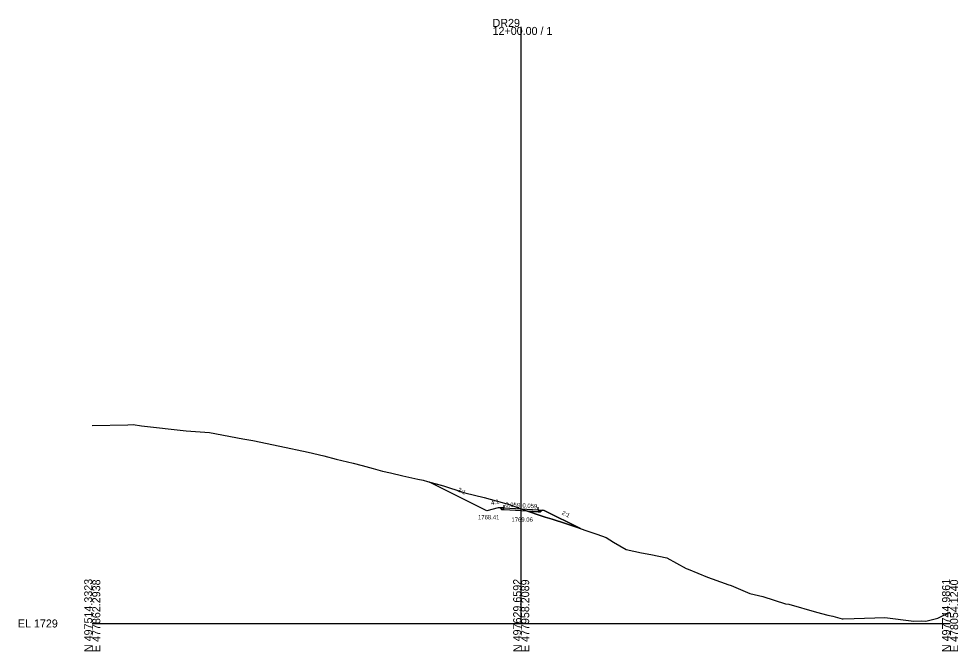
# Model space of a CAD drawing. Extents: x -26 to 303, y -10 to 4734.
# Drawn here: x -25.7 to 302.8, y 3990.3 to 4211.4 of the extents above; entities that cross this region are included whole.
import ezdxf

# ---------------------------------------------------------------- set-up
doc = ezdxf.new("R2010")
doc.units = 0
for name, color, linetype in [('Exist Cross Section Cell', 7, 'Continuous'), ('Exist XS Center Line Elevation Label', 7, 'Continuous'), ('Exist XS Ground Line', 7, 'Continuous'), ('Prop XS Ditch Slope Text', 7, 'Continuous'), ('Prop XS Ditch Standard Text', 7, 'Continuous'), ('Prop XS Dump Level', 7, 'Continuous'), ('Prop XS Earthwork Shape', 7, 'Continuous'), ('Prop XS EOT Tick Mark', 7, 'Continuous'), ('Prop XS Finish Grade', 7, 'Continuous'), ('Prop XS Finish Grade Earthwork', 7, 'Continuous'), ('Prop XS Finish Grade Pavement', 7, 'Continuous'), ('Prop XS Pvmt Edge Slope', 7, 'Continuous'), ('Prop XS SE Text', 7, 'Continuous'), ('Prop XS Shoulder Borrow Shape', 7, 'Continuous'), ('Prop XS Side Slope Text', 7, 'Continuous'), ('Prop XS Subgrade Earthwork', 7, 'Continuous')]:
    doc.layers.add(name, color=color, linetype=linetype)

msp = doc.modelspace()

# ---------------------------------------------------------------- linework, layer by layer
at = {"layer": 'Exist Cross Section Cell'}
for p, q in [((150, 4000), (150, 4208.57)), ((0, 4000), (150, 4000)), ((150, 4000), (300, 4000))]:
    msp.add_line(p, q, dxfattribs=at)
at = {"layer": 'Exist XS Ground Line'}
msp.add_lwpolyline([(0, 4069.23), (12.42, 4069.51), (14.36, 4069.52), (17.18, 4069.08), (32.86, 4067.4), (41.05, 4066.76), (52.7, 4064.58), (56.11, 4063.98), (65.64, 4062.03), (75.53, 4059.86), (80.98, 4058.57), (85.35, 4057.44), (91.27, 4056.08), (94.44, 4055.28), (98.25, 4054.18), (101.54, 4053.27), (104.28, 4052.64), (108.65, 4051.64), (113.89, 4050.5), (115.75, 4050.05), (117.29, 4049.63), (122.85, 4048.07), (129.54, 4045.91), (129.95, 4045.78), (130.3, 4045.72), (137.05, 4044.01), (143.31, 4042.31), (144.16, 4042.12), (145.18, 4041.78), (150, 4040.06), (151.26, 4039.61), (156.32, 4037.84), (158.36, 4037.17), (160.82, 4036.44), (165.46, 4034.97), (169.33, 4033.67), (172.57, 4032.53), (176.46, 4031.27), (179.67, 4030.04), (182.34, 4028.39), (186.77, 4025.87), (192.1, 4024.67), (195.34, 4024.08), (200.97, 4023), (207.75, 4019.24), (208.35, 4018.94), (215.18, 4016.16), (221.36, 4013.99), (222.28, 4013.68), (223.39, 4013.29), (229.99, 4010.47), (234.53, 4009.41), (242.48, 4006.88), (243.62, 4006.72), (253.33, 4003.94), (257.21, 4002.85), (258.4, 4002.68), (259, 4002.54), (262.23, 4001.64), (262.59, 4001.65), (266.41, 4001.76), (273.72, 4002.01), (277.23, 4002.07), (287.27, 4000.82), (290.05, 4000.91), (291.51, 4000.86), (295.69, 4001.81), (300, 4003.96)], dxfattribs=at)
at = {"layer": 'Prop XS Dump Level'}
for p, q in [((144, 4040.41), (150, 4040.06)), ((150, 4040.06), (156, 4039.7))]:
    msp.add_line(p, q, dxfattribs=at)
at = {"layer": 'Prop XS Earthwork Shape'}
for points in [[(138, 4039.41), (117.92, 4049.45), (122.85, 4048.07), (129.54, 4045.91), (129.95, 4045.78), (130.3, 4045.72), (137.05, 4044.01), (143.31, 4042.31), (144.16, 4042.12), (145.18, 4041.78), (150, 4040.06), (151.26, 4039.61), (152.27, 4039.25), (150, 4039.39), (144, 4039.74), (143.37, 4039.78), (142.74, 4040.41), (142, 4040.41)], [(138, 4039.41), (117.92, 4049.45), (122.85, 4048.07), (129.54, 4045.91), (129.95, 4045.78), (130.3, 4045.72), (137.05, 4044.01), (143.31, 4042.31), (144.16, 4042.12), (145.18, 4041.78), (150, 4040.06), (151.26, 4039.61), (152.27, 4039.25), (150, 4039.39), (144, 4039.74), (143.37, 4039.78), (142.74, 4040.41), (142, 4040.41)], [(156, 4039.03), (156.71, 4038.99), (157.31, 4039.6), (158, 4039.54), (170.73, 4033.18), (169.33, 4033.67), (165.46, 4034.97), (160.82, 4036.44), (158.36, 4037.17), (156.32, 4037.84), (152.27, 4039.25)], [(152.27, 4039.25), (156.32, 4037.84), (158.36, 4037.17), (160.82, 4036.44), (165.46, 4034.97), (169.33, 4033.67), (170.73, 4033.18), (158, 4039.54), (157.31, 4039.6), (156.71, 4038.99), (156, 4039.03)]]:
    msp.add_lwpolyline(points, close=True, dxfattribs=at)
at = {"layer": 'Prop XS EOT Tick Mark'}
for p, q in [((144, 4040.41), (144, 4041.41)), ((156, 4039.7), (156, 4040.7))]:
    msp.add_line(p, q, dxfattribs=at)
at = {"layer": 'Prop XS Finish Grade'}
for p, q in [((144, 4040.41), (142.74, 4040.41)), ((156, 4039.7), (157.31, 4039.6))]:
    msp.add_line(p, q, dxfattribs=at)
at = {"layer": 'Prop XS Finish Grade Earthwork'}
for p, q in [((138, 4039.41), (117.92, 4049.45)), ((142, 4040.41), (138, 4039.41)), ((142.74, 4040.41), (142, 4040.41)), ((157.31, 4039.6), (158, 4039.54)), ((158, 4039.54), (170.73, 4033.18))]:
    msp.add_line(p, q, dxfattribs=at)
at = {"layer": 'Prop XS Finish Grade Pavement'}
for p, q in [((144, 4040.41), (150, 4040.06)), ((150, 4040.06), (156, 4039.7))]:
    msp.add_line(p, q, dxfattribs=at)
at = {"layer": 'Prop XS Pvmt Edge Slope'}
for p, q in [((144, 4040.41), (143.37, 4039.78)), ((156, 4039.7), (156.71, 4038.99))]:
    msp.add_line(p, q, dxfattribs=at)
at = {"layer": 'Prop XS Shoulder Borrow Shape'}
for points in [[(144, 4040.41), (142.74, 4040.41), (143.37, 4039.78)], [(156, 4039.7), (157.31, 4039.6), (156.71, 4038.99)]]:
    msp.add_lwpolyline(points, close=True, dxfattribs=at)
at = {"layer": 'Prop XS Subgrade Earthwork'}
for p, q in [((143.37, 4039.78), (142.74, 4040.41)), ((144, 4039.74), (143.37, 4039.78)), ((150, 4039.39), (144, 4039.74)), ((156, 4039.03), (150, 4039.39)), ((156, 4039.03), (156.71, 4038.99)), ((156.71, 4038.99), (157.31, 4039.6))]:
    msp.add_line(p, q, dxfattribs=at)

# ---------------------------------------------------------------- texts
at = {"layer": 'Exist Cross Section Cell'}
for s, p in [('12+00.00 / 1', (140, 4205.77)), ('DR29', (140, 4208.57)), ('EL 1729', (-26, 3998.6))]:
    msp.add_text(s, height=2.8, dxfattribs=at).set_placement(p)
for s, p in [('N 497514.3323', (0, 3990)), ('E 477862.2938', (2.8, 3990)), ('N 497629.6592', (150, 3990)), ('E 477958.2089', (152.8, 3990)), ('N 497744.9861', (300, 3990)), ('E 478054.1240', (302.8, 3990))]:
    msp.add_text(s, height=2.8, rotation=90, dxfattribs=at).set_placement(p)
at = {"layer": 'Exist XS Center Line Elevation Label'}
msp.add_text('1769.06', height=1.5, dxfattribs=at).set_placement((146.6, 4035.56))
at = {"layer": 'Prop XS Ditch Slope Text'}
msp.add_text('4:1', height=1.5, rotation=14.0362, dxfattribs=at).set_placement((139.64, 4041.36))
at = {"layer": 'Prop XS Ditch Standard Text'}
msp.add_text('1768.41', height=1.5, dxfattribs=at).set_placement((134.91, 4036.41))
at = {"layer": 'Prop XS Dump Level'}
for p in [(142, 4040.37), (158, 4039.5)]:
    msp.add_text('Case1', height=0.04, dxfattribs=at).set_placement(p)
at = {"layer": 'Prop XS SE Text'}
for p in [(144.4, 4040.89), (150.4, 4040.53)]:
    msp.add_text('0.059', height=1.5, rotation=356.609, dxfattribs=at).set_placement(p)
at = {"layer": 'Prop XS Side Slope Text'}
for p in [(127.62, 4046.28), (164.02, 4038.21)]:
    msp.add_text('2:1', height=1.5, rotation=333.4349, dxfattribs=at).set_placement(p)

doc.saveas('drawing.dxf')
